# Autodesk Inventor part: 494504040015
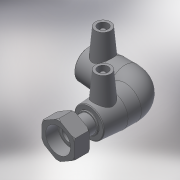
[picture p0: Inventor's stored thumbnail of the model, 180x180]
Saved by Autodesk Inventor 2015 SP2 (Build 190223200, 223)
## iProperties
Created: 2017-06
Part Number: 494504040015
Material: Generic
Description: PLASSON 90° ELBOW FEMALE FREE NUT TRANSITION 40-1.1/2"
Document SubType Name: Modeling
Designer: KIM
Mass: 55.0731 g
Surface Area: 148.067 cm^2
Volume: 55.0731 cm^3
Density: 1 g/cm^3
Appearance: Default
Author: KIM
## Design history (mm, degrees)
derived "494504.ipt"
feature "Solid1::494504.ipt"
tag "TaggingFeature1"
body "Solid1"
other parameters: "d2" = 56, "d4" = 30.66667, "d5" = 50.4, "d8" = 168 deg, "d10" = 17.6, "d11" = 5.86667, "d29" = 47, "d30" = 15, "d31" = 50.6, "d34" = 5 deg, "d41" = 4, "d42" = 14, "d43" = 0, "d48" = 64, "d50" = 34, "d51" = 17.6, "d52" = 44, "d54" = 90 deg, "d58" = 44, "d59" = 0, "d61" = 90 deg, "d86" = 3, "d87" = 0, "d97" = 29, "d99" = 67.2675, "d109" = 1.2, "d117" = 44.845, "d118" = 16, "d119" = 1.6, "d120" = 35.876, "d121" = 1.6, "d122" = 31.3915, "d123" = 29, "d124" = 2.24225, "d128" = 0, "L_" = 132, "L_1" = 44, "D_" = 29, "A_" = 47, "d_2" = 12, "D_1" = 56, "G_" = 44.845
